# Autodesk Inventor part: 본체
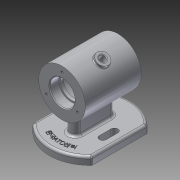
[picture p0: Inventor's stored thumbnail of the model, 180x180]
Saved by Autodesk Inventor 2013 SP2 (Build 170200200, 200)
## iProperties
Created: 2022-02
Part Number: 본체
Material: 알루미늄 6061
Document SubType Name: Modeling
Designer: i
Density: 2.71 g/cm^3
Mass: 497.101 g
Surface Area: 489.776 cm^2
Volume: 183.432 cm^3
Author: i
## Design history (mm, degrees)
sketch "스케치1"
  geometry: L1 (52, -38)-(-52, -38); L2 (-52, -38)-(-52, 38); L3 (-52, 38)-(52, 38); L4 (52, 38)-(52, -38); L5 (52, -38)-(-52, 38); L6 (-52, -38)-(52, 38); 1 further point
  constraints: 12 end point, 2 midpoint, 2 parallel, 1 horizontal, 1 perpendicular
  dimensions: "d0" = 104 distance of L2.end L3.end; "d1" = 76 distance of L1.end L2.end
extrude "돌출1" new body sketch "스케치1" distance "d2" = 10; taper "d3" = 0 deg
sketch "스케치2"
  geometry: C1 r 52 at (0, 0); 1 further point
  constraints: 1 centre point, 1 coincident
  dimensions: "d4" = 104 diameter of C1
extrude "돌출2" sketch "스케치2" distance "d5" = 10; taper "d6" = 0 deg
sketch "스케치3"
  geometry: L1 (-36, 92)-(36, 92); L2 (36, 92)-(36, 62); L3 (36, 62)-(-36, 62); L4 (-36, 62)-(-36, 92); 2 further points
  constraints: 8 end point, 2 parallel, 1 horizontal, 1 midpoint, 1 perpendicular, 1 vertical alignment
  dimensions: "d7" = 72 distance of L2.end L3.end; "d8" = 30 distance of L1.end L2.end; "d9" = 62 distance of point (0, 0) point (0, 62)
revolve "회전1" sketch "스케치3" stored, may be unused: angle "d10" = 90 deg
sketch "스케치4"
  geometry: C1 r 30 at (0, 0) reference; C2 r 16 at (0, 0); 1 further point
  constraints: 1 centre point, 1 coincident
  dimensions: "d11" = 32 diameter of C2
extrude "돌출3" cut sketch "스케치4" distance "d12" = 12; taper "d13" = 0 deg
sketch "스케치5"
  geometry: C1 r 16 at (0, 0) reference; C2 r 14 at (0, 0); 1 further point
  constraints: 1 centre point, 1 coincident
  dimensions: "d14" = 28 diameter of C2
extrude "돌출4" cut sketch "스케치5" distance "d15" = 4; taper "d16" = 0 deg
sketch "스케치6"
  geometry: C1 r 14 at (0, 0) reference; C2 r 25 at (0, 0); 1 further point
  constraints: 1 centre point, 1 coincident
  dimensions: "d17" = 50 diameter of C2
extrude "돌출5" cut sketch "스케치6" distance "d18" = 40; taper "d19" = 0 deg
fillet "모깎기1" dims "d20" = 3, "d21" = 0.3
sketch "스케치7"
  geometry: C1 r 16 at (0, 0) reference; 2 further points
  constraints: 1 vertical alignment
  dimensions: "d22" = 23 distance of C1.centre point (0, 23)
hole "구멍1" sketch "스케치7" at (0, 23) diameter "d23" = 3.242; stored, may be unused: countersink angle "d27" = 90 deg, drill point angle "d29" = 118 deg; dims "d24" = 8, "d25" = 4, "d26" = 2, "d28" = 10
sketch "스케치8"
  geometry: L1 (-19, 7)-(19, 7); L2 (19, 7)-(19, -7); L3 (19, -7)-(-19, -7); L4 (-19, -7)-(-19, 7); L5 (-19, 7)-(19, -7); L6 (19, 7)-(-19, -7); A1 r 52 centre (0, 0) between (-35.496, 38) and (-35.496, -38) reference; A2 r 7 centre (-19, 0) between (-19, 7) and (-19, -7); A3 r 7 centre (19, 0) between (19, -7) and (19, 7)
  constraints: 12 end point, 4 midpoint, 4 point on circle, 2 centre point, 2 parallel, 1 horizontal, 1 perpendicular
  dimensions: "d33" = 38 distance of L2.end L3.end; "d34" = 14 distance of L1.end L2.end
extrude "돌출6" join sketch "스케치8" stored distance "d35" = 40; taper "d36" = 0 deg
sketch "스케치9"
  geometry: L1 (-7.5, 28.5)-(7.5, 28.5); L2 (7.5, 28.5)-(7.5, 19.5); L3 (7.5, 19.5)-(-7.5, 19.5); L4 (-7.5, 19.5)-(-7.5, 28.5); L5 (-7.5, 28.5)-(7.5, 19.5); L6 (7.5, 28.5)-(-7.5, 19.5); L7 (-7.5, -19.5)-(7.5, -19.5); L8 (7.5, -19.5)-(7.5, -28.5); L9 (7.5, -28.5)-(-7.5, -28.5); L10 (-7.5, -28.5)-(-7.5, -19.5); L11 (-7.5, -19.5)-(7.5, -28.5); L12 (7.5, -19.5)-(-7.5, -28.5); A1 r 52 centre (0, 0) between (35.496, -38) and (35.496, 38) reference; A2 r 52 centre (0, 0) between (-35.496, 38) and (-35.496, -38) reference; A3 r 4.5 centre (-7.5, 24) between (-7.5, 28.5) and (-7.5, 19.5); A4 r 4.5 centre (7.5, 24) between (7.5, 19.5) and (7.5, 28.5); A5 r 4.5 centre (-7.5, -24) between (-7.5, -19.5) and (-7.5, -28.5); A6 r 4.5 centre (7.5, -24) between (7.5, -28.5) and (7.5, -19.5); 4 further points
  constraints: 24 end point, 10 midpoint, 8 point on circle, 4 centre point, 4 parallel, 2 horizontal, 2 perpendicular, 2 vertical alignment
  dimensions: "d37" = 15 distance of L2.end L3.end; "d38" = 9 distance of L1.end L2.end; "d39" = 24 distance of A1.centre point (0, 24); "d40" = 15 distance of L8.end L9.end; "d41" = 9 distance of L7.end L8.end; "d42" = 48 distance of point (0, -24) point (0, 24)
extrude "돌출7" cut sketch "스케치9" stored distance "d43" = 40; taper "d44" = 0 deg
sketch "스케치10"
  geometry: L1 (62, 0)-(90.579, 16.5); 2 further points
  constraints: 2 end point, 1 coincident
  dimensions: "d45" = 33 distance of L1.start L1.end
node "작업 평면1"
sketch "스케치11"
  geometry: L1 (36, 30)-(36, -30) reference; C1 r 8 at (0, 0); 1 further point
  constraints: 1 centre point
  dimensions: "d47" = 16 diameter of C1; "d63" = 36 distance from line of L1 C1.centre; "d64" = 31 distance of point (0, 31) C1.centre
extrude "돌출8" join sketch "스케치11" stored distance "d48" = 40; taper "d49" = 0 deg
sketch "스케치12"
  geometry: C1 r 8 at (0, 0) reference; C2 r 4 at (0, 0); 1 further point
  constraints: 1 centre point, 1 coincident
  dimensions: "d50" = 8 diameter of C2
extrude "돌출9" cut sketch "스케치12" stored distance "d51" = 40; taper "d52" = 0 deg
fillet "모깎기2" dims "d53" = 1
sketch "스케치13"
  geometry: C1 r 42.5 at (0, 0); A1 r 52 centre (0, 0) between (-35.496, 38) and (-35.496, -38) reference
  constraints: 1 centre point, 1 coincident, 1 other
  dimensions: "d54" = 85 diameter of C1
feature "엠보싱1" sketch "스케치13" dims "d0" = 104, "d1" = 76, "d55" = 0.5, "d56" = 0
chamfer "모따기1" distance "d57" = 1; stored, may be unused: second distance "d58" = 2, angle "d59" = 45 deg
fillet "모깎기3" dims "d60" = 3
fillet "모깎기4" dims "d61" = 3
fillet "모깎기5" dims "d62" = 3
node "솔리드1"
mirror "대칭1"
mirror "대칭2"
pattern_circular "원형 패턴1" dims angle "d31" = 360 deg
mirror "대칭3"
